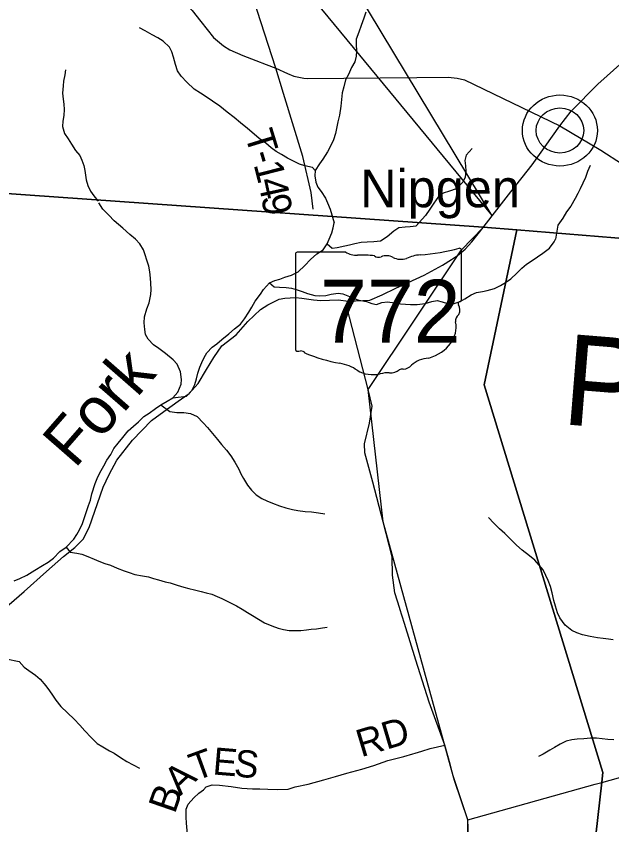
# Model space of a CAD drawing. Extents: x -139 to 835, y 0 to 440.
# Drawn here: x 127.4 to 167, y 290.4 to 344.1 of the extents above; entities that cross this region are included whole.
import ezdxf

# ---------------------------------------------------------------- set-up
doc = ezdxf.new("R2010")
doc.units = 0
for name, color, linetype in [('Default', 7, 'Continuous'), ('GM_X_County_Road', 7, 'Continuous'), ('GM_X_County_Text', 7, 'Continuous'), ('GM_X_Minor_River', 7, 'Continuous'), ('GM_X_Minor_River_Text', 7, 'Continuous'), ('GM_X_State_Location', 7, 'Continuous'), ('GM_X_State_Route', 7, 'Continuous'), ('GM_X_State_Shield', 7, 'Continuous'), ('GM_X_Township_Road', 7, 'Continuous'), ('GM_X_Township_Road_Text', 7, 'Continuous'), ('GM_X_Unincorporated', 7, 'Continuous'), ('GM_X_Unincorporated_Location', 7, 'Continuous'), ('GM_X_Unincorporated_Text', 7, 'Continuous'), ('SH_Cut_Line', 7, 'Continuous'), ('SH_Text', 7, 'Continuous')]:
    doc.layers.add(name, color=color, linetype=linetype)

msp = doc.modelspace()

# ---------------------------------------------------------------- linework, layer by layer
at = {"layer": 'Default'}
for p, q in [((150.787, 319.315), (157.002, 328.601)), ((151.799, 310.517), (150.787, 319.315)), ((156.46, 293.609), (151.799, 310.517)), ((157.423, 290.689), (156.46, 293.609)), ((157.828, 283.115), (157.423, 290.689))]:
    msp.add_line(p, q, dxfattribs=at)
at = {"layer": 'GM_X_County_Road'}
for points in [[(144.641, 340.684), (137.254, 363.525)], [(127.165, 349.341), (128.555, 348.774), (129.422, 348.448), (129.974, 348.292), (130.692, 348.278), (132.306, 348.292), (133.606, 348.179), (134.338, 348.066), (135.085, 347.825), (135.877, 347.329), (136.934, 346.483), (138.465, 345.135), (139.086, 344.52), (139.652, 343.787), (140.507, 342.714), (141.169, 342.177), (141.597, 341.903), (142.466, 341.523), (143.321, 341.196), (144.011, 340.921), (144.641, 340.684)], [(144.641, 340.684), (145.438, 340.326), (145.854, 340.154), (146.302, 340.055), (146.512, 340.028), (146.727, 339.991), (154.032, 340.065), (156.122, 340.073), (156.729, 340.023), (157.211, 339.904), (163.548, 336.843)], [(163.548, 336.843), (166.278, 335.235), (167.722, 334.302), (168.024, 334.061), (168.341, 333.594), (168.595, 333.052), (168.897, 332.571), (169.07, 332.384), (169.358, 332.21), (169.788, 332.102), (170.593, 331.911), (171.089, 331.705), (171.414, 331.456), (171.801, 331.133), (172.329, 330.652), (172.606, 330.457), (172.693, 330.399)], [(126.061, 304.297), (127.891, 305.87), (129.377, 307.205), (130.516, 308.194), (131.27, 308.79), (131.834, 309.35), (132.236, 310.13), (133.166, 312.81), (133.569, 313.662), (134.061, 314.598), (135.115, 315.937), (136.385, 317.239), (137.19, 317.845), (138.149, 318.534), (138.889, 319.045), (139.48, 319.702), (140.036, 320.649), (140.526, 321.428), (141.054, 322.206), (142.013, 322.956), (142.796, 323.84), (143.641, 324.627), (144.124, 324.941), (144.559, 325.166), (144.881, 325.318), (145.25, 325.381), (145.951, 325.435), (146.386, 325.39), (147.153, 325.282), (147.636, 325.228), (148.79, 325.264), (149.493, 325.19)]]:
    msp.add_lwpolyline(points, dxfattribs=at)
at = {"layer": 'GM_X_County_Text'}
msp.add_lwpolyline([(205.139, 401.486), (87.298, 401.486), (90.116, 391.109), (100.145, 354.177), (105.67, 333.828), (158.444, 330.1), (160.688, 329.921), (171.559, 329.033), (172.321, 330.669), (184.767, 357.384), (185.383, 358.364), (185.729, 359.048), (185.902, 359.821), (186.018, 360.334), (186.292, 360.95), (186.616, 361.275), (187.014, 361.689), (203.078, 396.689), (203.294, 397.153), (203.246, 397.371), (203.278, 397.973), (203.623, 399.152)], close=True, dxfattribs=at)
for points in [[(164.238, 274.594), (166.338, 293.196), (166.41, 293.836), (158.512, 319.627), (160.688, 329.921), (158.444, 330.1), (105.67, 333.828), (92.493, 334.759), (67.578, 336.518), (67.578, 185.387)], [(267.909, 321.538), (228.151, 324.569), (207.436, 326.102), (194.287, 327.176), (177.155, 328.576), (171.559, 329.033), (160.688, 329.921), (158.512, 319.627), (166.41, 293.836), (166.338, 293.196), (164.238, 274.594)]]:
    msp.add_lwpolyline(points, dxfattribs=at)
at = {"layer": 'GM_X_Minor_River'}
for points in [[(150.651, 344.406), (150.519, 344.01), (150.336, 343.518), (150.166, 343.086), (150.008, 342.605), (150.004, 342.28), (150.011, 341.822), (149.994, 341.472), (149.914, 341.112), (149.693, 340.716), (149.485, 340.261), (149.29, 339.901), (149.17, 339.432), (149.077, 339.036), (149.021, 338.602), (148.977, 338.157), (148.881, 337.567), (148.774, 337.11), (148.613, 336.341), (148.481, 335.92), (148.26, 335.453), (148.091, 335.117), (147.781, 334.626), (147.561, 334.315), (147.265, 333.873), (147.248, 333.523), (147.318, 333.1), (147.454, 332.774), (147.678, 332.47), (147.964, 332.032), (148.087, 331.73), (148.259, 331.294), (148.545, 330.394)], [(147.265, 333.873), (147.102, 334.067), (146.584, 334.182), (146.218, 334.306), (145.865, 334.467), (145.425, 334.701), (145.022, 334.946), (144.683, 335.143), (144.343, 335.388), (143.98, 335.705), (143.54, 336), (143.201, 336.293), (142.775, 336.659), (142.311, 337.038), (141.885, 337.405), (141.42, 337.759), (140.918, 338.151), (140.428, 338.494), (140.014, 338.776), (139.636, 339.009), (139.222, 339.291), (138.733, 339.754), (138.358, 340.144), (138.109, 340.497), (137.974, 340.92), (137.841, 341.416), (137.719, 341.767), (137.583, 342.082), (137.145, 342.485), (136.793, 342.705), (136.415, 342.891), (135.949, 343.161), (135.584, 343.37)], [(130.659, 340.58), (130.604, 340.243), (130.523, 339.81), (130.493, 339.497), (130.462, 339.015), (130.508, 338.629), (130.542, 338.279), (130.563, 337.929), (130.545, 337.544), (130.477, 337.159), (130.448, 336.809), (130.594, 336.338), (130.83, 335.985), (131.054, 335.633), (131.327, 335.196), (131.602, 334.868), (131.75, 334.553), (131.873, 334.214), (131.945, 333.887), (131.992, 333.574), (132.026, 333.248), (132.135, 332.885), (132.32, 332.497), (132.545, 332.193), (132.819, 331.84)], [(157.724, 335.346), (157.326, 334.893), (157.233, 334.532), (157.266, 334.194), (157.287, 333.832), (157.244, 333.435), (157.101, 333.111), (156.665, 332.658), (156.219, 332.506), (155.799, 332.366), (155.48, 332.141), (155.158, 331.699), (154.899, 331.304), (154.615, 330.885), (153.988, 330.197)], [(165.579, 334.198), (165.384, 333.802), (165.253, 333.418), (164.901, 332.662), (164.745, 332.35), (164.564, 332.003), (164.279, 331.5), (164.008, 331.129), (163.762, 330.71), (163.427, 330.232), (163.272, 329.319)], [(127.242, 306.583), (127.624, 306.738), (128.068, 306.964), (128.615, 307.287), (129.124, 307.597), (129.493, 307.824), (129.862, 308.099), (130.283, 308.531), (130.703, 308.829), (131.201, 309.345), (131.405, 309.657), (131.585, 309.97), (131.777, 310.402), (132.035, 311.124), (132.178, 311.594), (132.319, 311.954), (132.411, 312.376), (132.631, 313.05), (132.798, 313.495), (133.016, 313.915), (133.196, 314.228), (133.413, 314.6), (133.669, 314.996), (133.874, 315.393), (134.155, 315.729), (134.475, 316.125), (134.82, 316.557), (135.176, 316.88), (135.52, 317.167), (135.865, 317.503), (136.221, 317.73), (136.641, 318.041), (136.997, 318.28), (137.417, 318.542), (137.786, 318.757), (138.118, 319.129), (138.349, 319.658), (138.376, 319.983), (138.316, 320.478), (138.079, 320.986), (137.827, 321.289), (137.298, 321.702), (136.856, 322.042), (136.516, 322.285), (136.163, 322.661), (135.988, 322.963), (135.927, 323.301), (135.879, 323.736), (135.907, 324.133), (136.062, 324.675), (136.217, 325.072), (136.334, 325.625), (136.349, 325.951), (136.326, 326.385), (136.303, 326.711), (136.268, 327.133), (136.194, 327.507), (136.07, 327.906), (135.958, 328.256), (135.834, 328.606), (135.595, 328.993), (135.306, 329.309), (134.94, 329.612), (134.474, 330.049), (133.894, 330.523), (133.529, 330.899), (133.139, 331.311), (132.876, 331.722)], [(137.786, 318.757), (138.705, 318.857), (139.061, 319.232), (139.252, 319.642), (139.366, 320.017), (139.468, 320.403), (139.596, 320.802), (139.735, 321.104), (139.888, 321.43), (140.066, 321.744), (140.41, 322.118), (140.727, 322.348), (141.058, 322.626), (141.516, 323.012), (141.897, 323.338), (142.291, 323.652), (142.571, 324.002), (142.851, 324.461), (143.055, 324.787), (143.284, 325.174), (143.627, 325.645), (143.831, 325.971), (144.237, 326.394), (144.593, 326.551), (144.911, 326.659), (145.254, 326.78), (145.699, 326.913), (146.132, 327.142), (146.577, 327.565), (146.958, 327.964), (147.378, 328.326), (147.797, 328.604), (148.065, 328.99), (148.204, 329.316), (148.383, 329.739), (148.459, 330.053), (148.545, 330.394)], [(148.065, 328.99), (148.395, 328.712), (148.738, 328.761), (149.234, 328.869), (149.552, 328.942), (149.92, 329.014), (150.327, 329.099), (150.734, 329.135), (151.179, 329.159), (151.623, 329.207), (152.056, 329.497), (152.514, 329.871), (152.831, 330.077), (153.251, 330.137), (153.594, 330.149), (153.988, 330.197)], [(144.237, 326.394), (144.53, 326.14), (144.898, 326.116), (145.343, 326.104), (145.686, 326.055), (146.004, 325.971), (146.398, 325.838), (146.766, 325.693), (147.237, 325.572), (147.567, 325.548), (147.987, 325.572), (148.33, 325.657), (148.8, 325.717), (149.118, 325.669), (149.55, 325.499), (149.868, 325.354), (150.185, 325.246), (150.694, 325.173), (151.037, 325.028), (151.355, 324.968), (151.698, 325.088), (152.092, 325.149), (152.562, 325.064), (152.956, 325.016), (153.617, 324.967), (154.049, 324.967), (154.583, 325.04), (155.041, 325.161), (155.397, 325.233), (155.727, 325.148), (156.083, 325.028), (156.515, 325.04), (156.922, 325.16), (157.24, 325.341), (157.646, 325.595), (158.002, 325.752), (158.396, 325.837), (158.714, 325.885), (159.197, 326.018), (159.604, 326.223), (159.947, 326.416), (160.303, 326.67), (160.698, 327.044), (161.016, 327.382), (161.333, 327.636), (161.715, 327.889), (162.071, 328.143), (162.427, 328.372), (162.859, 328.711), (163.177, 329.121), (163.272, 329.319)], [(136.997, 318.28), (137.586, 317.855), (138.056, 317.782), (138.539, 317.77), (138.971, 317.71), (139.416, 317.504), (139.81, 317.094), (140.102, 316.78), (140.445, 316.393), (140.762, 315.982), (141.029, 315.656), (141.359, 315.282), (141.652, 314.895), (141.918, 314.484), (142.185, 314.001), (142.325, 313.699), (142.502, 313.385), (142.756, 312.938), (143.023, 312.612), (143.353, 312.298), (143.722, 312.068), (144.052, 311.911), (144.434, 311.742), (144.904, 311.561), (145.323, 311.44), (145.768, 311.331), (146.111, 311.271), (146.594, 311.198), (147.026, 311.162), (147.496, 311.102), (147.916, 311.041)], [(167.104, 302.668), (166.786, 302.704), (166.443, 302.741), (166.062, 302.789), (165.579, 302.886), (165.071, 302.994), (164.677, 303.115), (164.359, 303.284), (163.902, 303.623), (163.559, 304.13), (163.394, 304.444), (163.267, 304.891), (163.165, 305.278), (163.038, 305.785), (162.937, 306.196), (162.785, 306.607), (162.632, 306.945), (162.442, 307.307), (162.175, 307.633), (161.883, 307.96), (161.54, 308.25), (161.057, 308.612), (160.676, 308.95), (160.358, 309.264), (159.888, 309.735), (159.545, 310.049), (159.151, 310.424), (158.796, 310.786)], [(130.703, 308.829), (130.972, 308.482), (131.417, 308.433), (131.734, 308.361), (132.141, 308.204), (132.56, 308.023), (132.878, 307.89), (133.272, 307.745), (133.64, 307.624), (134.085, 307.418), (134.568, 307.237), (134.898, 307.128), (135.267, 307.008), (135.775, 306.911), (136.182, 306.839), (136.5, 306.742), (136.843, 306.645), (137.275, 306.524), (137.618, 306.44), (138.076, 306.295), (138.533, 306.162), (138.851, 306.077), (139.245, 305.981), (139.677, 305.872), (140.007, 305.787), (140.401, 305.691), (140.744, 305.546), (141.062, 305.401), (141.545, 305.159), (142.028, 304.929), (142.409, 304.7), (142.765, 304.482), (143.095, 304.277), (143.489, 304.023), (143.896, 303.782), (144.378, 303.588), (144.798, 303.443), (145.154, 303.347), (145.548, 303.286), (145.954, 303.274), (146.323, 303.274), (146.692, 303.322), (147.009, 303.359), (147.353, 303.395), (147.747, 303.455), (148.077, 303.503)], [(126.71, 301.391), (127.574, 301.222), (127.904, 300.835), (128.222, 300.618), (128.654, 300.316), (128.972, 300.038), (129.353, 299.603), (129.594, 299.277), (129.785, 298.975), (130, 298.649), (130.343, 298.214), (131.22, 297.38), (131.601, 296.982), (131.931, 296.595), (132.363, 296.172), (132.77, 295.773), (133.138, 295.532), (133.583, 295.278), (133.901, 295.109), (134.32, 294.831), (134.726, 294.565), (135.159, 294.336), (135.578, 294.118)], [(167.139, 296), (166.757, 296.024), (166.363, 296.072), (165.995, 296.109), (165.601, 296.121), (165.143, 296.084), (164.698, 296.048), (164.342, 296.012), (163.974, 295.928), (163.58, 295.722), (163.198, 295.505), (162.88, 295.312), (162.448, 295.058), (162.13, 294.889)]]:
    msp.add_lwpolyline(points, dxfattribs=at)
at = {"layer": 'GM_X_State_Route'}
for p, q in [((158.451, 330.084), (159.052, 330.859)), ((156.46, 293.609), (156.248, 294.397))]:
    msp.add_line(p, q, dxfattribs=at)
for points in [[(159.052, 330.859), (160.294, 332.461), (161.707, 334.257), (163.548, 336.843), (164.297, 337.814), (166.091, 339.625), (167.744, 341.108), (169.456, 342.731)], [(152.905, 304.749), (152.579, 305.788), (152.419, 306.961), (152.399, 308.18), (151.799, 310.517), (151.114, 313.156), (150.584, 315.094), (150.555, 315.686), (150.88, 317.069), (151.062, 318.201), (150.787, 319.315), (149.377, 324.816), (149.493, 325.19), (150.901, 325.246), (151.739, 325.614), (152.644, 326.052), (154.53, 326.912), (155.748, 327.58), (156.339, 327.957), (156.742, 328.22), (157.264, 328.65), (157.703, 329.132), (158.451, 330.084)], [(156.248, 294.397), (155.91, 295.658), (154.857, 298.506), (153.972, 301.305), (153.221, 303.74), (152.915, 304.718), (152.905, 304.749)], [(155.494, 255.352), (154, 260.041), (153.734, 260.918), (153.723, 261.18), (153.809, 261.553), (154.76, 263.76), (155.975, 266.11), (156.256, 267.059), (156.365, 268.323), (156.444, 270.074), (156.505, 272.693), (156.591, 275.057), (156.703, 276.637), (157.341, 278.584), (157.836, 280.243), (157.891, 281.401), (157.828, 283.115), (157.59, 285.906), (157.414, 288.612), (157.423, 290.689), (156.545, 293.294), (156.46, 293.609)]]:
    msp.add_lwpolyline(points, dxfattribs=at)
at = {"layer": 'GM_X_State_Shield'}
for p, q in [((145.958, 328.329), (145.958, 321.969)), ((149.301, 328.438), (146.066, 328.438)), ((157.002, 325.269), (157.002, 328.596)), ((157.001, 325.27), (157.002, 325.269))]:
    msp.add_line(p, q, dxfattribs=at)
for centre, major_axis, start_param, end_param in [((153.068, 337.108), (11.713, 0), 4.814394, 5.042369), ((156.88, 328.609), (0.123, 0), 6.141152, 7.989035), ((146.084, 328.342), (0.128, 0), 1.712693, 3.28349), ((150.071, 329.176), (1.241, 0), 4.042523, 4.731795), ((150.483, 324.868), (4.455, 0), 1.404758, 1.657858), ((151.494, 328.375), (0.358, 0), 3.836095, 5.185415), ((152.02, 327.64), (0.744, 0), 0.950623, 2.079405), ((154.562, 326.496), (2.356, 0), 1.699011, 2.107814), ((152.981, 328.648), (0.896, 0), 4.081561, 5.145723), ((156.974, 325.025), (0.19, 0), 1.883978, 3.671073), ((155.763, 324.604), (1.142, 0), 5.934695, 6.695948), ((156.871, 325.256), (0.132, 0), 5.05454, 6.418171), ((157.443, 323.876), (0.831, 0), 2.387724, 3.262537), ((153.724, 323.453), (2.93, 0), 5.101752, 6.440018), ((146.085, 321.955), (0.129, 0), 3.00124, 4.508301), ((146.105, 322.606), (0.985, 0), 4.665946, 4.897461), ((146.306, 321.602), (0.355, 0), 0.519207, 1.627899), ((150.791, 327.316), (8.458, 0), 4.195997, 4.488961), ((154.96, 320.183), (1.605, 0), 1.647645, 2.488434), ((148.269, 319.112), (2.646, 0), 0.823519, 1.323587), ((151.132, 321.57), (1.679, 0), 4.026481, 4.996735), ((152.225, 321.094), (0.895, 0), 4.691044, 5.507374), ((153.034, 320.478), (0.252, 0), 1.147584, 2.315152), ((152.927, 321.352), (0.947, 0), 4.937069, 5.64225), ((152.102, 319.372), (1.38, 0), 1.495662, 1.94098)]:
    msp.add_ellipse(centre, major_axis=major_axis, ratio=0.758645, start_param=start_param, end_param=end_param, dxfattribs=at)
at = {"layer": 'GM_X_Township_Road'}
msp.add_line((157.423, 290.689), (165.905, 293.057), dxfattribs=at)
for points in [[(147.135, 331.313), (147, 332.42), (146.453, 334.806), (145.161, 339.004), (144.641, 340.684)], [(165.905, 293.057), (166.345, 293.179), (184.632, 298.284)], [(153.936, 295.117), (154.359, 295.252), (154.931, 295.427), (155.91, 295.658)], [(144.774, 292.712), (145.472, 292.717), (145.942, 292.881), (146.793, 293.065), (147.849, 293.343), (148.624, 293.576), (149.387, 293.797), (150.366, 294.064), (151.167, 294.297), (152.109, 294.637), (153.164, 294.891), (153.774, 295.065), (153.936, 295.117)], [(138.201, 288.234), (138.451, 288.328), (138.592, 288.411), (138.746, 288.579), (138.836, 288.759), (138.839, 289.024), (138.716, 290.461), (138.683, 290.859), (138.689, 291.39), (138.82, 291.738), (139.192, 292.144), (139.525, 292.455), (139.844, 292.68), (140.011, 292.872), (140.418, 293.012), (140.912, 292.983), (141.684, 292.902), (142.38, 292.798), (143.089, 292.742), (143.583, 292.737), (144.116, 292.72), (144.774, 292.712)]]:
    msp.add_lwpolyline(points, dxfattribs=at)
at = {"layer": 'GM_X_Unincorporated'}
for major_axis in [(2.493, 0), (1.581, 0)]:
    msp.add_ellipse((163.559, 336.536), major_axis=major_axis, ratio=0.948307, dxfattribs=at)
at = {"layer": 'GM_X_Unincorporated_Location'}
msp.add_line((163.559, 336.536), (163.559, 336.536), dxfattribs=at)
at = {"layer": 'SH_Cut_Line'}
for points in [[(295.458, 319.381), (295.458, 401.486), (67.578, 401.486), (67.578, 336.518), (92.493, 334.759), (105.67, 333.828), (158.444, 330.1), (160.688, 329.921), (171.559, 329.033), (177.155, 328.576), (194.287, 327.176), (207.436, 326.102), (228.151, 324.569), (267.909, 321.538)], [(67.578, 336.518), (67.578, 185.387), (295.458, 185.387), (295.458, 319.381), (267.909, 321.538), (228.151, 324.569), (207.436, 326.102), (194.287, 327.176), (177.155, 328.576), (171.559, 329.033), (160.688, 329.921), (158.444, 330.1), (105.67, 333.828), (92.493, 334.759)]]:
    msp.add_lwpolyline(points, close=True, dxfattribs=at)
at = {"layer": 'SH_Text'}
msp.add_line((157.002, 328.596), (158.451, 330.084), dxfattribs=at)
msp.add_lwpolyline([(159.052, 330.859), (131.176, 377.048), (131.176, 364.607)], close=True, dxfattribs=at)

# ---------------------------------------------------------------- texts
at = {"layer": 'GM_X_County_Text'}
msp.add_text('PIKE COUNTY', height=6.02285, rotation=355.3985, dxfattribs=at).set_placement((163.594, 317.011))
at = {"layer": 'GM_X_Minor_River_Text'}
msp.add_text('Fork', height=3.1352, rotation=48.878, dxfattribs=at).set_placement((131.269, 313.992))
at = {"layer": 'GM_X_State_Location'}
for s in ['s', 'r']:
    msp.add_text(s, height=0.00602, dxfattribs=at).set_placement((151.356, 324.726))
msp.add_text('772', height=0.00602, rotation=0, dxfattribs=at).set_placement((149.115, 324.288))
at = {"layer": 'GM_X_State_Shield'}
msp.add_text('772', height=4.1897, dxfattribs=at).set_placement((147.599, 322.417))
at = {"layer": 'GM_X_Township_Road_Text'}
for s, height, rotation, p in [('T', 1.902, 287.0335, (142.564, 336.276)), ('-', 1.902, 286.2376, (142.959, 334.985)), ('1', 1.902, 284.3231, (143.163, 334.285)), ('4', 1.903, 282.3652, (143.436, 333.219)), ('9', 1.903, 280.1178, (143.671, 332.148)), ('RD', 1.8204, 16.6486, (150.329, 294.841)), ('T', 1.826, 20.0025, (139.304, 293.258)), ('E', 1.807, 355.2215, (140.409, 293.712)), ('S', 1.808, 353.8112, (141.815, 293.595)), ('A', 1.872, 43.2461, (138.288, 292.246)), ('B', 1.901, 70.9177, (137.925, 291.027))]:
    msp.add_text(s, height=height, rotation=rotation, dxfattribs=at).set_placement(p)
at = {"layer": 'GM_X_Unincorporated_Text'}
msp.add_text('Nipgen', height=2.5099, rotation=0, dxfattribs=at).set_placement((150.26, 331.432))

doc.saveas('drawing.dxf')
